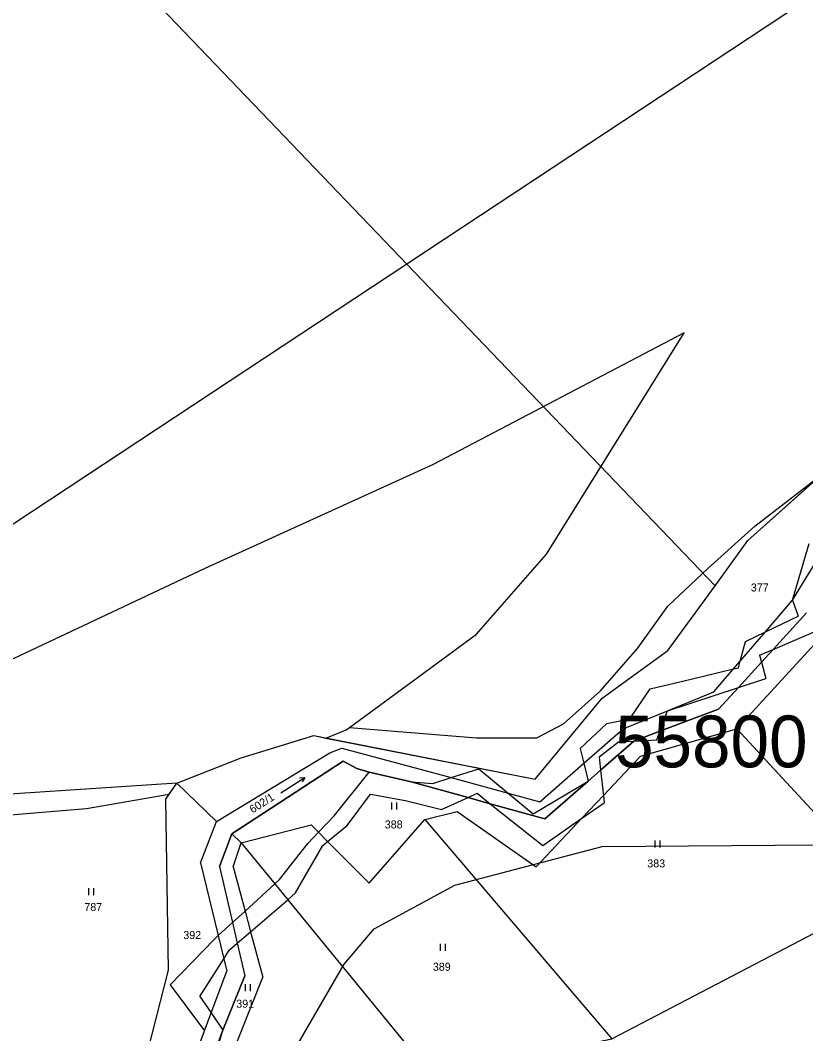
# Model space of a CAD drawing. Extents: x -725765 to -723182, y -1052705 to -1049154.
# Drawn here: x -723941.9 to -723775.1, y -1052129.8 to -1051914.6 of the extents above; entities that cross this region are included whole.
import ezdxf

# ---------------------------------------------------------------- set-up
doc = ezdxf.new("R2010")
doc.units = 0
for name, color, linetype in [('Vrstva 1', 7, 'Continuous'), ('Vrstva 12', 7, 'Continuous'), ('Vrstva 18', 7, 'Continuous'), ('Vrstva 25', 7, 'Continuous'), ('Vrstva 4', 7, 'Continuous'), ('Vrstva 52', 7, 'Continuous'), ('Vrstva 53', 7, 'Continuous')]:
    doc.layers.add(name, color=color, linetype=linetype)

msp = doc.modelspace()

# ---------------------------------------------------------------- linework, layer by layer
at = {"layer": 'Vrstva 1'}
for points in [[(-724028.07, -1051790.82), (-723794.32, -1052034.7)], [(-723787.35, -1052025.08), (-723769.86, -1052009.42)], [(-723794.32, -1052034.7), (-723787.35, -1052025.08)], [(-723777.86, -1052037.76), (-723769.37, -1052023.84)], [(-723804.35, -1052048.42), (-723794.32, -1052034.7)], [(-723783.63, -1052044.46), (-723777.86, -1052037.76)], [(-723781.98, -1052048.21), (-723774.9, -1052040.47)], [(-723789.72, -1052065.09), (-723770.63, -1052044.28)], [(-723789.01, -1052050.71), (-723783.63, -1052044.46)], [(-723818.32, -1052058.55), (-723804.35, -1052048.42)], [(-723784.48, -1052050.94), (-723781.98, -1052048.21)], [(-723790.44, -1052052.37), (-723789.01, -1052050.71)], [(-723789.39, -1052056.3), (-723784.48, -1052050.94)], [(-723794.63, -1052057.24), (-723790.44, -1052052.37)], [(-723804.46, -1052061.27), (-723796.18, -1052057.88)], [(-723796.18, -1052057.88), (-723794.63, -1052057.24)], [(-723793.63, -1052060.93), (-723789.39, -1052056.3)], [(-723832.56, -1052075.75), (-723818.32, -1052058.55)], [(-723813.84, -1052065.08), (-723804.46, -1052061.27)], [(-723806.04, -1052065.6), (-723793.63, -1052060.93)], [(-723894.94, -1052071.26), (-723879.55, -1052066.53)], [(-723879.55, -1052066.53), (-723832.56, -1052075.75)], [(-723822.19, -1052072.39), (-723813.84, -1052065.08)], [(-723811.58, -1052067.68), (-723806.04, -1052065.6)], [(-723810.17, -1052070.87), (-723789.72, -1052065.09)], [(-723789.72, -1052065.09), (-723757.29, -1052100.11)], [(-723818.65, -1052073.88), (-723811.58, -1052067.68)], [(-723900.18, -1052084.74), (-723876.14, -1052070.19)], [(-723876.14, -1052070.19), (-723873.56, -1052069.16)], [(-723873.56, -1052069.16), (-723850.41, -1052075.44)], [(-723818.06, -1052079.25), (-723810.17, -1052070.87)], [(-723908.6, -1052076.65), (-723894.94, -1052071.26)], [(-723896.93, -1052087.37), (-723873.33, -1052071.97)], [(-723873.33, -1052071.97), (-723870.43, -1052073.5)], [(-723831.52, -1052080.57), (-723822.19, -1052072.39)], [(-723870.43, -1052073.5), (-723867.78, -1052074.32)], [(-723867.78, -1052074.32), (-723858.9, -1052076.31)], [(-723850.41, -1052075.44), (-723838.26, -1052078.74)], [(-723821.27, -1052076.18), (-723818.65, -1052073.88)], [(-723908.6, -1052076.65), (-723960.29, -1052080)], [(-723910.94, -1052080), (-723908.6, -1052076.65)], [(-723908.6, -1052076.65), (-723900.18, -1052084.74)], [(-723858.9, -1052076.31), (-723846.78, -1052079.67)], [(-723830.5, -1052084.18), (-723821.27, -1052076.18)], [(-723846.78, -1052079.67), (-723842.07, -1052080.98)], [(-723838.26, -1052078.74), (-723831.52, -1052080.57)], [(-723822.61, -1052084.08), (-723818.06, -1052079.25)], [(-723910.43, -1052116.31), (-723910.94, -1052080)], [(-723842.07, -1052080.98), (-723830.5, -1052084.18)], [(-723855.94, -1052084.33), (-723849.12, -1052082.64)], [(-723849.12, -1052082.64), (-723832.34, -1052094.42)], [(-723903.61, -1052093.54), (-723900.18, -1052084.74)], [(-723894.99, -1052089.27), (-723880.09, -1052085.48)], [(-723880.09, -1052085.48), (-723878.55, -1052087.03)], [(-723867.8, -1052097.89), (-723855.94, -1052084.33)], [(-723855.94, -1052084.33), (-723816.27, -1052130.96)], [(-723832.34, -1052094.42), (-723822.61, -1052084.08)], [(-723899.6, -1052094.3), (-723896.93, -1052087.37)], [(-723896.93, -1052087.37), (-723894.99, -1052089.27)], [(-723878.55, -1052087.03), (-723876.62, -1052088.98)], [(-723896.67, -1052094.38), (-723894.99, -1052089.27)], [(-723894.99, -1052089.27), (-723887.84, -1052098.01)], [(-723876.62, -1052088.98), (-723867.8, -1052097.89)], [(-723903.61, -1052093.54), (-723899.86, -1052109)], [(-723899.6, -1052094.3), (-723896.81, -1052106.22)], [(-723896.67, -1052094.38), (-723894.15, -1052103.78)], [(-723887.84, -1052098.01), (-723885.09, -1052101.38)], [(-723816.27, -1052130.96), (-723757.29, -1052100.11)], [(-723885.09, -1052101.38), (-723851.81, -1052142.06)], [(-723894.15, -1052103.78), (-723892.97, -1052108.17)], [(-723896.81, -1052106.22), (-723895.79, -1052110.6)], [(-723899.86, -1052109), (-723898.67, -1052113.93)], [(-723892.97, -1052108.17), (-723890.37, -1052117.86)], [(-723895.79, -1052110.6), (-723894.17, -1052117.53)], [(-723898.67, -1052113.93), (-723898.04, -1052116.53)], [(-723914.73, -1052133.27), (-723910.43, -1052116.31)], [(-723901.9, -1052146.83), (-723890.37, -1052117.86)], [(-723901.35, -1052125.43), (-723898.04, -1052116.53)], [(-723898.85, -1052129.07), (-723894.17, -1052117.53)], [(-723902.77, -1052129.23), (-723901.35, -1052125.43)], [(-723906.42, -1052139.07), (-723902.77, -1052129.23)], [(-723904.2, -1052143.54), (-723898.85, -1052129.07)]]:
    msp.add_lwpolyline(points, dxfattribs=at)
at = {"layer": 'Vrstva 12'}
msp.add_lwpolyline([(-724065.44, -1052102.13), (-723775.56, -1051910.67)], dxfattribs=at)
at = {"layer": 'Vrstva 25'}
for points in [[(-723886.52, -1052078.66), (-723881.48, -1052075.4)], [(-723882.59, -1052075.52), (-723881.48, -1052075.4), (-723882.05, -1052076.36)], [(-723862.96, -1052082.23), (-723862.96, -1052080.73)], [(-723861.92, -1052082.23), (-723861.92, -1052080.73)], [(-723807.05, -1052090.3), (-723807.05, -1052088.8)], [(-723806.01, -1052090.3), (-723806.01, -1052088.8)], [(-723927.32, -1052100.44), (-723927.32, -1052098.94)], [(-723926.28, -1052100.44), (-723926.28, -1052098.94)], [(-723852.61, -1052112.27), (-723852.61, -1052110.77)], [(-723851.57, -1052112.27), (-723851.57, -1052110.77)], [(-723894.04, -1052120.79), (-723894.04, -1052119.29)], [(-723893, -1052120.79), (-723893, -1052119.29)]]:
    msp.add_lwpolyline(points, dxfattribs=at)
at = {"layer": 'Vrstva 4'}
for points in [[(-723777.86, -1052037.76), (-723774.35, -1052025.73)], [(-723777.86, -1052037.76), (-723776.71, -1052041.12)], [(-723783.63, -1052044.46), (-723776.71, -1052041.12)], [(-723787.87, -1052046.51), (-723783.63, -1052044.46)], [(-723781.98, -1052048.21), (-723771.34, -1052043.66)], [(-723789.01, -1052050.71), (-723787.87, -1052046.51)], [(-723784.88, -1052049.45), (-723781.98, -1052048.21)], [(-723784.88, -1052049.45), (-723784.48, -1052050.94)], [(-723789.39, -1052052.12), (-723789.01, -1052050.71)], [(-723784.48, -1052050.94), (-723783.56, -1052054.38)], [(-723799.15, -1052054.44), (-723790.44, -1052052.37)], [(-723790.44, -1052052.37), (-723789.39, -1052052.12)], [(-723808.14, -1052056.57), (-723799.15, -1052054.44)], [(-723789.39, -1052056.3), (-723783.56, -1052054.38)], [(-723812.4, -1052062.99), (-723808.14, -1052056.57)], [(-723804.46, -1052061.27), (-723789.39, -1052056.3)], [(-723806.04, -1052065.6), (-723804.46, -1052061.27)], [(-723822.95, -1052069.25), (-723817.3, -1052063.93)], [(-723817.3, -1052063.93), (-723812.4, -1052062.99)], [(-723806.69, -1052067.39), (-723806.04, -1052065.6)], [(-723818.96, -1052071.05), (-723814.81, -1052067.87)], [(-723814.81, -1052067.87), (-723811.58, -1052067.68)], [(-723811.58, -1052067.68), (-723806.69, -1052067.39)], [(-723822.95, -1052069.25), (-723822.19, -1052072.39)], [(-723818.96, -1052071.05), (-723818.65, -1052073.88)], [(-723822.19, -1052072.39), (-723821.27, -1052076.18)], [(-723875.19, -1052083.54), (-723867.78, -1052074.32)], [(-723854.29, -1052076.67), (-723850.41, -1052075.44)], [(-723850.41, -1052075.44), (-723844.53, -1052073.58)], [(-723844.53, -1052073.58), (-723838.26, -1052078.74)], [(-723818.65, -1052073.88), (-723818.06, -1052079.25)], [(-723858.9, -1052076.31), (-723854.29, -1052076.67)], [(-723832.94, -1052083.12), (-723821.27, -1052076.18)], [(-723872.49, -1052085.59), (-723867.53, -1052078.97)], [(-723867.53, -1052078.97), (-723860.05, -1052080.27)], [(-723852.43, -1052082.23), (-723846.78, -1052079.67)], [(-723846.78, -1052079.67), (-723844.83, -1052078.78)], [(-723844.83, -1052078.78), (-723842.07, -1052080.98)], [(-723838.26, -1052078.74), (-723832.94, -1052083.12)], [(-723818.06, -1052079.25), (-723817.89, -1052080.82)], [(-723860.05, -1052080.27), (-723852.43, -1052082.23)], [(-723842.07, -1052080.98), (-723830.92, -1052089.83)], [(-723822.61, -1052084.08), (-723817.89, -1052080.82)], [(-723878.55, -1052087.03), (-723875.19, -1052083.54)], [(-723876.62, -1052088.98), (-723872.49, -1052085.59)], [(-723830.92, -1052089.83), (-723822.61, -1052084.08)], [(-723880.84, -1052089.41), (-723878.55, -1052087.03)], [(-723886.81, -1052097.07), (-723880.84, -1052089.41)], [(-723883.42, -1052099.94), (-723877.66, -1052089.84)], [(-723877.66, -1052089.84), (-723876.62, -1052088.98)], [(-723894.15, -1052103.78), (-723887.84, -1052098.01)], [(-723887.84, -1052098.01), (-723886.81, -1052097.07)], [(-723885.09, -1052101.38), (-723883.42, -1052099.94)], [(-723892.97, -1052108.17), (-723885.09, -1052101.38)], [(-723896.81, -1052106.22), (-723894.15, -1052103.78)], [(-723899.86, -1052109), (-723896.81, -1052106.22)], [(-723910.03, -1052119.43), (-723900.66, -1052109.73)], [(-723900.66, -1052109.73), (-723899.86, -1052109)], [(-723895.79, -1052110.6), (-723892.97, -1052108.17)], [(-723897.49, -1052112.07), (-723895.79, -1052110.6)], [(-723903.74, -1052121.95), (-723898.67, -1052113.93)], [(-723898.67, -1052113.93), (-723897.49, -1052112.07)], [(-723910.03, -1052119.43), (-723902.77, -1052129.23)], [(-723903.74, -1052121.95), (-723901.35, -1052125.43)], [(-723901.35, -1052125.43), (-723898.85, -1052129.07)], [(-723901.62, -1052138.54), (-723898.85, -1052129.07)]]:
    msp.add_lwpolyline(points, dxfattribs=at)
at = {"layer": 'Vrstva 52'}
for points in [[(-723872, -1052064.82), (-723858.63, -1052055), (-723845, -1052045), (-723830.13, -1052028), (-723800.88, -1051981), (-723854.31, -1052009), (-723902.69, -1052031), (-723955.81, -1052056), (-723987.81, -1052070), (-724017.81, -1052081), (-724044.81, -1052088), (-724071.13, -1052091), (-724107.5, -1052091), (-724131.69, -1052089), (-724148.13, -1052085), (-724163.81, -1052078), (-724181.88, -1052066)], [(-723876.98, -1052067.03), (-723832.56, -1052075.75), (-723818.32, -1052058.55), (-723804.35, -1052048.42), (-723794.32, -1052034.7), (-723787.35, -1052025.08), (-723771.62, -1052011)], [(-723872, -1052064.82), (-723845, -1052067), (-723832.19, -1052067), (-723826.5, -1052064), (-723818.63, -1052057), (-723810.81, -1052048), (-723804.38, -1052039), (-723795.88, -1052031), (-723785.88, -1052022), (-723771.62, -1052011)], [(-723774.9, -1052040.47), (-723781.98, -1052048.21), (-723784.48, -1052050.94), (-723789.39, -1052056.3), (-723793.63, -1052060.93), (-723806.04, -1052065.6), (-723811.58, -1052067.68), (-723818.65, -1052073.88), (-723821.27, -1052076.18), (-723830.5, -1052084.18), (-723842.07, -1052080.98), (-723846.78, -1052079.67), (-723858.9, -1052076.31), (-723867.78, -1052074.32), (-723870.43, -1052073.5), (-723873.33, -1052071.97), (-723896.93, -1052087.37), (-723899.6, -1052094.3), (-723896.81, -1052106.22), (-723895.79, -1052110.6), (-723894.17, -1052117.53), (-723898.85, -1052129.07), (-723904.2, -1052143.54)], [(-723910.23, -1052078.98), (-723908.6, -1052076.65), (-723894.94, -1052071.26), (-723879.55, -1052066.53), (-723876.98, -1052067.03)], [(-723876.98, -1052067.03), (-723872.68, -1052065.32), (-723872, -1052064.82)], [(-724102.57, -1052226.97), (-724094.97, -1052220.93), (-724086.67, -1052217.06), (-724083.68, -1052216.19), (-724059.51, -1052209.19), (-724048.17, -1052219.4), (-724039.36, -1052217.61), (-724044.72, -1052211.91), (-724026.1, -1052206.3), (-724009.71, -1052194.73), (-724004.89, -1052192.09), (-723992.25, -1052185.16), (-723964.25, -1052171.44), (-723946.29, -1052163.74), (-723944.23, -1052162.49), (-723932.21, -1052155.18), (-723914.73, -1052133.27), (-723910.43, -1052116.31), (-723910.94, -1052080), (-723910.23, -1052078.98)], [(-723976.88, -1052093.1), (-723970.63, -1052089), (-723951.69, -1052084), (-723927.81, -1052082), (-723910.23, -1052078.98)], [(-723903.23, -1052170.85), (-723889.27, -1052164.88), (-723867.8, -1052158.24), (-723849.51, -1052153.98), (-723851.81, -1052142.06), (-723833.83, -1052134.61), (-723816.27, -1052130.96), (-723757.29, -1052100.11), (-723726.26, -1052089.34)], [(-723903.23, -1052170.85), (-723890.98, -1052145.98), (-723873.08, -1052115.04), (-723866.75, -1052107.59), (-723849.6, -1052098.27), (-723818.29, -1052090.07), (-723772.44, -1052089.69), (-723726.26, -1052089.34)]]:
    msp.add_lwpolyline(points, dxfattribs=at)

# ---------------------------------------------------------------- texts
at = {"layer": 'Vrstva 18'}
for s, p in [('377', (-723786.74, -1052035.91)), ('388', (-723864.48, -1052086.24)), ('383', (-723808.73, -1052094.52)), ('787', (-723928.28, -1052103.77)), ('392', (-723907.26, -1052109.73)), ('389', (-723854.27, -1052116.47)), ('391', (-723896.02, -1052124.32))]:
    msp.add_text(s, height=1.7, dxfattribs=at).set_placement(p)
msp.add_text('602/1', height=1.7, rotation=32.4003, dxfattribs=at).set_placement((-723892.54, -1052083.09))
at = {"layer": 'Vrstva 53'}
msp.add_text('55800', height=11, dxfattribs=at).set_placement((-723815.59, -1052073.26))

doc.saveas('drawing.dxf')
